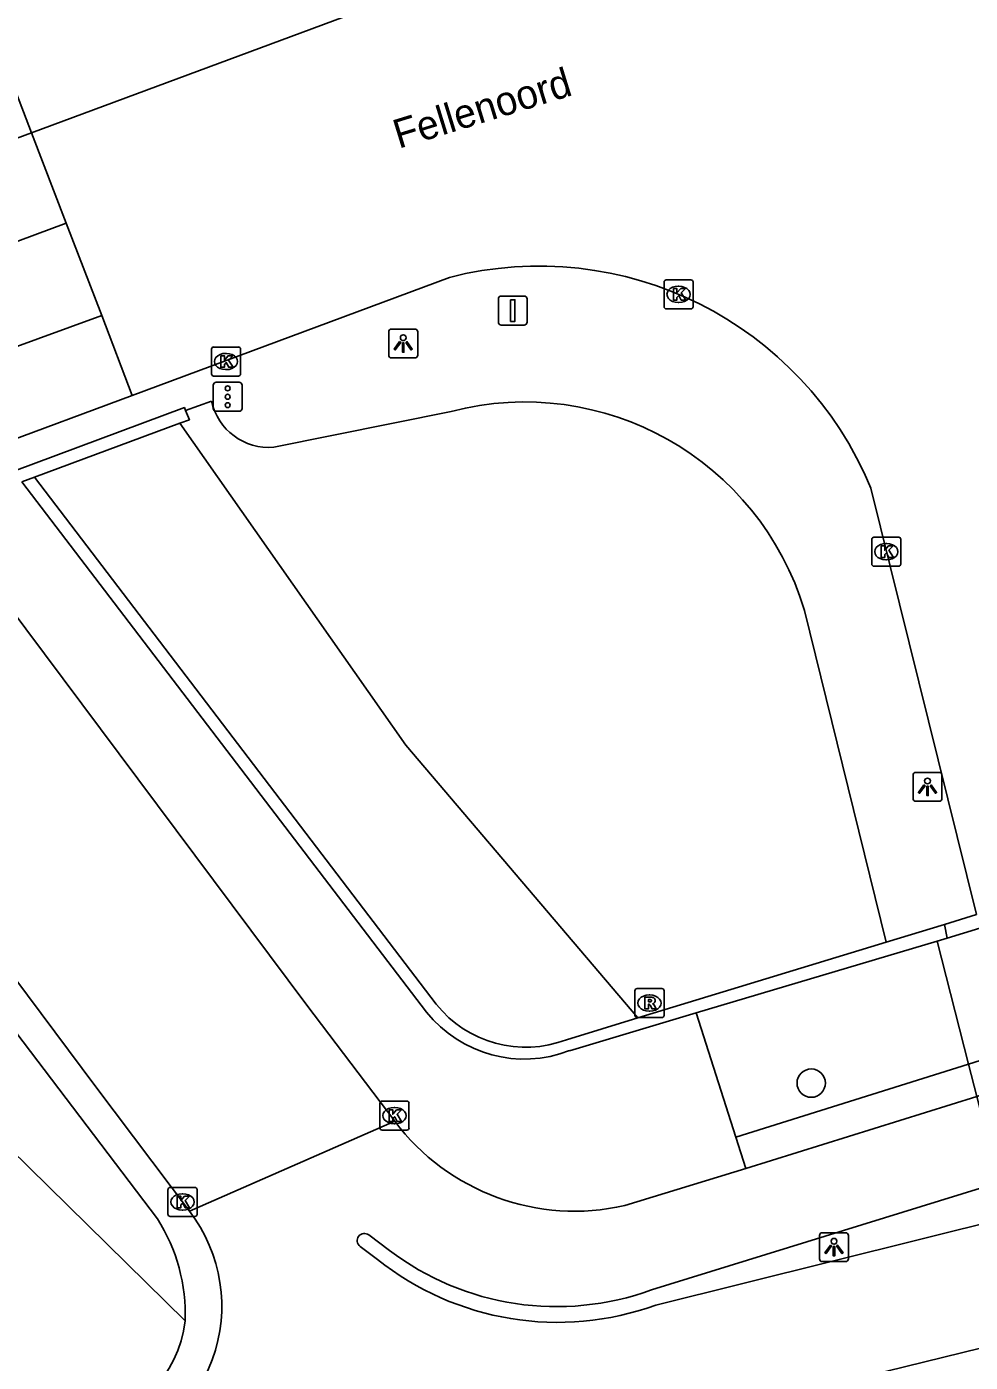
# Model space of a CAD drawing. Extents: x 160806 to 161707, y 383697 to 384148.
# Drawn here: x 160923.82 to 160956.33, y 383760.06 to 383806.1 of the extents above; entities that cross this region are included whole.
import ezdxf

# ---------------------------------------------------------------- set-up
doc = ezdxf.new("R2010")
doc.units = 0
for name, color, linetype in [('IMGEO_Berm_groen', 7, 'Continuous'), ('IMGEO_Boom', 7, 'Continuous'), ('IMGEO_Dek', 7, 'Continuous'), ('IMGEO_Fietspad_open', 7, 'Continuous'), ('IMGEO_Groenvoorziening', 7, 'Continuous'), ('IMGEO_Kolk', 7, 'Continuous'), ('IMGEO_Lichtpunt', 7, 'Continuous'), ('IMGEO_Muur', 7, 'Continuous'), ('IMGEO_Openbare_ruimte_label', 7, 'Continuous'), ('IMGEO_Portaal', 7, 'Continuous'), ('IMGEO_Rijbaan_lokaal_gesloten', 7, 'Continuous'), ('IMGEO_Rioolput', 7, 'Continuous'), ('IMGEO_Verkeersregelinstallatiepaal', 7, 'Continuous'), ('IMGEO_Voetpad_gesloten', 7, 'Continuous'), ('IMGEO_Voetpad_open', 7, 'Continuous')]:
    doc.layers.add(name, color=color, linetype=linetype)

msp = doc.modelspace()

# ---------------------------------------------------------------- linework, layer by layer
at = {"layer": 'IMGEO_Berm_groen'}
msp.add_lwpolyline([(161049.357, 383799.265), (161036.436, 383795.305), (161012.779, 383787.972), (161000, 383783.977), (160984.412, 383779.104), (160968.351, 383774.113), (160967.332, 383773.795), (160957.725, 383770.797), (160956.274, 383770.344), (160948.254, 383767.825)], dxfattribs=at)
at = {"layer": 'IMGEO_Boom'}
msp.add_circle((160950.851, 383769.687), 0.489, dxfattribs=at)
at = {"layer": 'IMGEO_Dek'}
msp.add_lwpolyline([(160956.543, 383775.501), (160955.438, 383775.157), (160955.538, 383774.68), (160955.193, 383774.577), (160956.274, 383770.344), (160956.559, 383769.228)], dxfattribs=at)
at = {"layer": 'IMGEO_Fietspad_open'}
for points in [[(161049.506, 383798.192), (161019.729, 383788.913), (160968.627, 383772.989), (160967.617, 383772.674), (160958.007, 383769.679), (160956.559, 383769.228), (160948.598, 383766.747)], [(160947.606, 383758.324), (160957.999, 383760.873), (160958.651, 383761.038), (160960.089, 383761.401), (160969.85, 383763.865), (160970.809, 383764.107), (160986.327, 383768.025), (161022.896, 383777.258), (161039.914, 383781.555), (161040.772, 383781.738)], [(160945.348, 383762.558), (160957.316, 383766.263), (160958.754, 383766.709), (160966.401, 383769.076)], [(160966.901, 383767.371), (160959.078, 383765.421), (160957.624, 383765.058), (160945.5, 383762.036)], [(160948.598, 383766.747), (160944.425, 383765.465)], [(160935.603, 383764.453), (160936.315, 383763.919)], [(160935.901, 383763.609), (160935.306, 383764.058)]]:
    msp.add_lwpolyline(points, dxfattribs=at)
for centre, radius, start, end in [((160942.706, 383773.033), 7.761, 216.8838, 282.7952), ((160925.172, 383761.997), 5.368, 282.2012, 37.6103), ((160935.454, 383764.256), 0.247, 53.0605, 233.0605), ((160942.106, 383771.399), 9.959, 231.4625, 289.9247), ((160942.082, 383771.536), 9.554, 232.8721, 289.9913)]:
    msp.add_arc(centre, radius, start, end, dxfattribs=at)
at = {"layer": 'IMGEO_Groenvoorziening'}
for points in [[(160944.875, 383771.933), (160936.888, 383781.34), (160929.1, 383792.432)], [(160929.276, 383761.487), (160906.384, 383783.994)]]:
    msp.add_lwpolyline(points, dxfattribs=at)
at = {"layer": 'IMGEO_Kolk'}
for p, q in [((160945.781, 383796.45), (160945.781, 383797.302)), ((160945.856, 383797.376), (160946.708, 383797.376)), ((160946.269, 383797.156), (160946.294, 383797.156)), ((160946.782, 383797.302), (160946.782, 383796.45)), ((160946.708, 383796.376), (160945.856, 383796.376)), ((160946.292, 383796.596), (160946.267, 383796.596)), ((160930.185, 383794.135), (160930.185, 383794.987)), ((160930.26, 383795.061), (160931.112, 383795.061)), ((160930.673, 383794.841), (160930.698, 383794.841)), ((160931.186, 383794.987), (160931.186, 383794.135)), ((160931.112, 383794.061), (160930.26, 383794.061)), ((160930.696, 383794.281), (160930.671, 383794.281)), ((160952.938, 383787.58), (160952.938, 383788.432)), ((160953.013, 383788.506), (160953.865, 383788.506)), ((160953.939, 383788.432), (160953.939, 383787.58)), ((160953.426, 383788.286), (160953.451, 383788.286)), ((160953.865, 383787.506), (160953.013, 383787.506)), ((160953.449, 383787.726), (160953.424, 383787.726)), ((160936.065, 383769.066), (160936.917, 383769.066)), ((160935.99, 383768.14), (160935.99, 383768.992)), ((160936.478, 383768.846), (160936.503, 383768.846)), ((160936.991, 383768.992), (160936.991, 383768.14)), ((160936.501, 383768.286), (160936.476, 383768.286)), ((160936.917, 383768.066), (160936.065, 383768.066)), ((160928.687, 383765.163), (160928.687, 383766.015)), ((160928.762, 383766.089), (160929.614, 383766.089)), ((160929.175, 383765.869), (160929.2, 383765.869)), ((160929.688, 383766.015), (160929.688, 383765.163)), ((160929.614, 383765.089), (160928.762, 383765.089)), ((160929.198, 383765.309), (160929.173, 383765.309))]:
    msp.add_line(p, q, dxfattribs=at)
for points in [[(160945.781, 383796.45), (160945.781, 383797.302)], [(160945.856, 383797.376), (160946.708, 383797.376)], [(160946.782, 383797.302), (160946.782, 383796.45)], [(160946.102, 383797.076), (160946.225, 383797.076), (160946.225, 383796.925), (160946.355, 383797.076), (160946.519, 383797.076), (160946.373, 383796.925), (160946.526, 383796.676), (160946.374, 383796.676), (160946.289, 383796.84), (160946.225, 383796.773), (160946.225, 383796.676), (160946.102, 383796.676), (160946.102, 383797.076)], [(160946.708, 383796.376), (160945.856, 383796.376)], [(160930.185, 383794.135), (160930.185, 383794.987)], [(160930.26, 383795.061), (160931.112, 383795.061)], [(160931.186, 383794.987), (160931.186, 383794.135)], [(160930.506, 383794.761), (160930.629, 383794.761), (160930.629, 383794.61), (160930.759, 383794.761), (160930.923, 383794.761), (160930.777, 383794.61), (160930.93, 383794.361), (160930.778, 383794.361), (160930.693, 383794.525), (160930.629, 383794.458), (160930.629, 383794.361), (160930.506, 383794.361), (160930.506, 383794.761)], [(160931.112, 383794.061), (160930.26, 383794.061)], [(160952.938, 383787.58), (160952.938, 383788.432)], [(160953.013, 383788.506), (160953.865, 383788.506)], [(160953.939, 383788.432), (160953.939, 383787.58)], [(160953.259, 383788.206), (160953.382, 383788.206), (160953.382, 383788.055), (160953.512, 383788.206), (160953.676, 383788.206), (160953.53, 383788.055), (160953.683, 383787.806), (160953.531, 383787.806), (160953.446, 383787.97), (160953.382, 383787.903), (160953.382, 383787.806), (160953.259, 383787.806), (160953.259, 383788.206)], [(160953.865, 383787.506), (160953.013, 383787.506)], [(160936.065, 383769.066), (160936.917, 383769.066)], [(160935.99, 383768.14), (160935.99, 383768.992)], [(160936.311, 383768.766), (160936.434, 383768.766), (160936.434, 383768.615), (160936.564, 383768.766), (160936.728, 383768.766), (160936.582, 383768.615), (160936.735, 383768.366), (160936.583, 383768.366), (160936.498, 383768.53), (160936.434, 383768.463), (160936.434, 383768.366), (160936.311, 383768.366), (160936.311, 383768.766)], [(160936.991, 383768.992), (160936.991, 383768.14)], [(160936.917, 383768.066), (160936.065, 383768.066)], [(160928.687, 383765.163), (160928.687, 383766.015)], [(160928.762, 383766.089), (160929.614, 383766.089)], [(160929.688, 383766.015), (160929.688, 383765.163)], [(160929.008, 383765.789), (160929.131, 383765.789), (160929.131, 383765.638), (160929.261, 383765.789), (160929.425, 383765.789), (160929.279, 383765.638), (160929.432, 383765.389), (160929.28, 383765.389), (160929.195, 383765.553), (160929.131, 383765.486), (160929.131, 383765.389), (160929.008, 383765.389), (160929.008, 383765.789)], [(160929.614, 383765.089), (160928.762, 383765.089)]]:
    msp.add_lwpolyline(points, dxfattribs=at)
for centre, start, end in [((160945.858, 383797.3), 91.552, 178.448), ((160945.858, 383797.3), 91.552, 178.448), ((160946.706, 383797.3), 1.552, 88.448), ((160946.706, 383797.3), 1.552, 88.448), ((160945.858, 383796.452), 181.552, 268.448), ((160945.858, 383796.452), 181.552, 268.448), ((160946.706, 383796.452), 271.552, 358.448), ((160946.706, 383796.452), 271.552, 358.448), ((160930.262, 383794.985), 91.552, 178.448), ((160930.262, 383794.985), 91.552, 178.448), ((160931.11, 383794.985), 1.552, 88.448), ((160931.11, 383794.985), 1.552, 88.448), ((160930.262, 383794.137), 181.552, 268.448), ((160930.262, 383794.137), 181.552, 268.448), ((160931.11, 383794.137), 271.552, 358.448), ((160931.11, 383794.137), 271.552, 358.448), ((160953.015, 383788.43), 91.552, 178.448), ((160953.015, 383788.43), 91.552, 178.448), ((160953.863, 383788.43), 1.552, 88.448), ((160953.863, 383788.43), 1.552, 88.448), ((160953.015, 383787.582), 181.552, 268.448), ((160953.015, 383787.582), 181.552, 268.448), ((160953.863, 383787.582), 271.552, 358.448), ((160953.863, 383787.582), 271.552, 358.448), ((160936.067, 383768.99), 91.552, 178.448), ((160936.067, 383768.99), 91.552, 178.448), ((160936.915, 383768.99), 1.552, 88.448), ((160936.915, 383768.99), 1.552, 88.448), ((160936.067, 383768.142), 181.552, 268.448), ((160936.067, 383768.142), 181.552, 268.448), ((160936.915, 383768.142), 271.552, 358.448), ((160936.915, 383768.142), 271.552, 358.448), ((160928.764, 383766.013), 91.552, 178.448), ((160928.764, 383766.013), 91.552, 178.448), ((160929.612, 383766.013), 1.552, 88.448), ((160929.612, 383766.013), 1.552, 88.448), ((160928.764, 383765.165), 181.552, 268.448), ((160928.764, 383765.165), 181.552, 268.448), ((160929.612, 383765.165), 271.552, 358.448), ((160929.612, 383765.165), 271.552, 358.448)]:
    msp.add_arc(centre, 0.0765, start, end, dxfattribs=at)
for centre, major_axis, ratio, start_param, end_param in [((160946.268, 383796.876), (-0.387, 0.002), 0.722429, 4.712389, 7.853982), ((160946.293, 383796.876), (-0.39, 0.002), 0.717154, 1.570796, 4.712389), ((160930.672, 383794.561), (-0.387, 0.002), 0.722429, 4.712389, 7.853982), ((160930.697, 383794.561), (-0.39, 0.002), 0.717154, 1.570796, 4.712389), ((160953.425, 383788.006), (-0.387, 0.002), 0.722429, 4.712389, 7.853982), ((160953.45, 383788.006), (-0.39, 0.002), 0.717154, 1.570796, 4.712389), ((160936.477, 383768.566), (-0.387, 0.002), 0.722429, 4.712389, 7.853982), ((160936.502, 383768.566), (-0.39, 0.002), 0.717154, 1.570796, 4.712389), ((160929.174, 383765.589), (-0.387, 0.002), 0.722429, 4.712389, 7.853982), ((160929.199, 383765.589), (-0.39, 0.002), 0.717154, 1.570796, 4.712389)]:
    msp.add_ellipse(centre, major_axis=major_axis, ratio=ratio, start_param=start_param, end_param=end_param, dxfattribs=at)
at = {"layer": 'IMGEO_Lichtpunt'}
for p, q in [((160936.295, 383795.584), (160936.295, 383794.777)), ((160936.295, 383795.584), (160936.295, 383794.777)), ((160937.197, 383795.679), (160936.389, 383795.679)), ((160937.197, 383795.679), (160936.389, 383795.679)), ((160937.291, 383794.777), (160937.291, 383795.584)), ((160937.291, 383794.777), (160937.291, 383795.584)), ((160936.389, 383794.683), (160937.197, 383794.683)), ((160936.389, 383794.683), (160937.197, 383794.683)), ((160954.36, 383780.303), (160954.36, 383779.496)), ((160954.36, 383780.303), (160954.36, 383779.496)), ((160955.262, 383780.398), (160954.454, 383780.398)), ((160955.262, 383780.398), (160954.454, 383780.398)), ((160955.356, 383779.496), (160955.356, 383780.303)), ((160955.356, 383779.496), (160955.356, 383780.303)), ((160954.454, 383779.402), (160955.262, 383779.402)), ((160954.454, 383779.402), (160955.262, 383779.402)), ((160952.039, 383764.531), (160951.231, 383764.531)), ((160952.039, 383764.531), (160951.231, 383764.531)), ((160951.137, 383764.436), (160951.137, 383763.629)), ((160951.137, 383764.436), (160951.137, 383763.629)), ((160952.133, 383763.629), (160952.133, 383764.436)), ((160952.133, 383763.629), (160952.133, 383764.436)), ((160951.231, 383763.535), (160952.039, 383763.535)), ((160951.231, 383763.535), (160952.039, 383763.535))]:
    msp.add_line(p, q, dxfattribs=at)
for points in [[(160936.669, 383795.248), (160936.708, 383795.22), (160936.52, 383794.958), (160936.482, 383794.985), (160936.669, 383795.248)], [(160936.771, 383795.2), (160936.818, 383795.2), (160936.818, 383794.878), (160936.771, 383794.878), (160936.771, 383795.2)], [(160936.881, 383795.22), (160936.919, 383795.247), (160937.106, 383794.985), (160937.067, 383794.957), (160936.881, 383795.22)], [(160954.734, 383779.967), (160954.773, 383779.939), (160954.585, 383779.677), (160954.547, 383779.704), (160954.734, 383779.967)], [(160954.836, 383779.919), (160954.883, 383779.919), (160954.883, 383779.597), (160954.836, 383779.597), (160954.836, 383779.919)], [(160954.946, 383779.939), (160954.984, 383779.966), (160955.171, 383779.704), (160955.132, 383779.676), (160954.946, 383779.939)], [(160951.511, 383764.1), (160951.55, 383764.072), (160951.362, 383763.81), (160951.324, 383763.837), (160951.511, 383764.1)], [(160951.613, 383764.052), (160951.66, 383764.052), (160951.66, 383763.73), (160951.613, 383763.73), (160951.613, 383764.052)], [(160951.723, 383764.072), (160951.761, 383764.099), (160951.948, 383763.837), (160951.909, 383763.809), (160951.723, 383764.072)]]:
    msp.add_lwpolyline(points, dxfattribs=at)
for centre in [(160936.794, 383795.382), (160954.859, 383780.101), (160951.636, 383764.234)]:
    msp.add_circle(centre, 0.0994, dxfattribs=at)
for centre, start, end in [((160936.389, 383795.584), 90, 180), ((160936.389, 383795.584), 90, 180), ((160937.197, 383795.584), 0, 90), ((160937.197, 383795.584), 0, 90), ((160936.389, 383794.777), 180, 270), ((160936.389, 383794.777), 180, 270), ((160937.197, 383794.777), 270, 0), ((160937.197, 383794.777), 270, 360), ((160954.454, 383780.303), 90, 180), ((160954.454, 383780.303), 90, 180), ((160955.262, 383780.303), 0, 90), ((160955.262, 383780.303), 0, 90), ((160954.454, 383779.496), 180, 270), ((160954.454, 383779.496), 180, 270), ((160955.262, 383779.496), 270, 0), ((160955.262, 383779.496), 270, 360), ((160951.231, 383764.436), 90, 180), ((160951.231, 383764.436), 90, 180), ((160952.039, 383764.436), 0, 90), ((160952.039, 383764.436), 0, 90), ((160951.231, 383763.629), 180, 270), ((160951.231, 383763.629), 180, 270), ((160952.039, 383763.629), 270, 0), ((160952.039, 383763.629), 270, 360)]:
    msp.add_arc(centre, 0.0946, start, end, dxfattribs=at)
at = {"layer": 'IMGEO_Muur'}
for points in [[(161041.832, 383801.291), (161039.53, 383800.843), (160967.312, 383778.34), (160966.993, 383778.241), (160966.263, 383778.014), (160956.661, 383775.029), (160955.538, 383774.68), (160955.193, 383774.577), (160946.889, 383772.105)], [(160923.377, 383790.783), (160929.252, 383792.972), (160929.293, 383792.872)], [(160929.293, 383792.872), (160929.426, 383792.553), (160929.1, 383792.432)], [(160929.1, 383792.432), (160924.086, 383790.569)], [(160924.086, 383790.569), (160923.655, 383790.409)], [(160937.594, 383772.128), (160923.655, 383790.409)], [(160924.086, 383790.569), (160937.932, 383772.405)], [(160953.439, 383774.547), (160955.438, 383775.157), (160956.543, 383775.501)], [(160944.875, 383771.933), (160953.439, 383774.547)], [(160942.421, 383771.184), (160944.875, 383771.933)], [(160946.889, 383772.105), (160942.522, 383770.805)]]:
    msp.add_lwpolyline(points, dxfattribs=at)
for centre, radius, start, end in [((160941.011, 383774.862), 3.939, 218.5892, 290.9783), ((160940.963, 383774.838), 4.323, 218.8083, 291.1365)]:
    msp.add_arc(centre, radius, start, end, dxfattribs=at)
at = {"layer": 'IMGEO_Portaal'}
for p, q in [((160940.071, 383795.917), (160940.071, 383796.717)), ((160940.071, 383796.717), (160940.071, 383795.917)), ((160940.171, 383796.817), (160940.961, 383796.817)), ((160940.961, 383796.817), (160940.171, 383796.817)), ((160941.061, 383796.717), (160941.061, 383795.917)), ((160941.061, 383795.917), (160941.061, 383796.717)), ((160940.961, 383795.817), (160940.171, 383795.817)), ((160940.171, 383795.817), (160940.961, 383795.817))]:
    msp.add_line(p, q, dxfattribs=at)
msp.add_lwpolyline([(160940.491, 383796.692), (160940.641, 383796.692), (160940.641, 383795.942), (160940.491, 383795.942), (160940.491, 383796.692)], dxfattribs=at)
for centre, start, end in [((160940.171, 383796.717), 90, 180), ((160940.171, 383796.717), 90, 180), ((160940.961, 383796.717), 0, 90), ((160940.961, 383796.717), 360, 90), ((160940.171, 383795.917), 180, 270), ((160940.171, 383795.917), 180, 270), ((160940.961, 383795.917), 270, 0), ((160940.961, 383795.917), 270, 0)]:
    msp.add_arc(centre, 0.1, start, end, dxfattribs=at)
at = {"layer": 'IMGEO_Rijbaan_lokaal_gesloten'}
for points in [[(160923.983, 383802.443), (160957.325, 383814.835)], [(160923.983, 383802.443), (160922.851, 383805.392)], [(160923.983, 383802.443), (160916.701, 383799.758)], [(160925.177, 383799.334), (160923.983, 383802.443)], [(160925.177, 383799.334), (160918.784, 383796.957)], [(160926.402, 383796.144), (160925.177, 383799.334)], [(160938.382, 383797.46), (160927.458, 383793.395)], [(160926.402, 383796.144), (160920.882, 383794.138)], [(160927.458, 383793.395), (160926.402, 383796.144)], [(160922.74, 383791.639), (160927.458, 383793.395)], [(160956.543, 383775.501), (160952.902, 383790.2)], [(160936.499, 383768.375), (160933.47, 383772.374), (160922.492, 383787.071), (160920.782, 383789.342)], [(160913.472, 383786.627), (160926.2, 383769.556), (160929.425, 383765.273)], [(160936.499, 383768.375), (160929.425, 383765.273)]]:
    msp.add_lwpolyline(points, dxfattribs=at)
msp.add_arc((160941.467, 383785.48), 12.371, 22.4294, 104.4404, dxfattribs=at)
at = {"layer": 'IMGEO_Rioolput'}
for p, q in [((160944.778, 383772.02), (160944.778, 383772.872)), ((160944.853, 383772.946), (160945.705, 383772.946)), ((160945.779, 383772.872), (160945.779, 383772.02)), ((160945.266, 383772.726), (160945.291, 383772.726)), ((160945.705, 383771.946), (160944.853, 383771.946)), ((160945.289, 383772.166), (160945.264, 383772.166))]:
    msp.add_line(p, q, dxfattribs=at)
for points in [[(160944.778, 383772.02), (160944.778, 383772.872)], [(160944.853, 383772.946), (160945.705, 383772.946)], [(160945.779, 383772.872), (160945.779, 383772.02)], [(160945.367, 383772.644), (160945.115, 383772.646), (160945.115, 383772.246)], [(160945.115, 383772.246), (160945.239, 383772.246), (160945.239, 383772.408), (160945.25, 383772.408)], [(160945.293, 383772.565), (160945.239, 383772.565), (160945.239, 383772.484)], [(160945.239, 383772.484), (160945.291, 383772.484)], [(160945.297, 383772.379), (160945.368, 383772.246), (160945.508, 383772.246), (160945.443, 383772.372)], [(160945.705, 383771.946), (160944.853, 383771.946)]]:
    msp.add_lwpolyline(points, dxfattribs=at)
for centre, radius, start, end in [((160944.855, 383772.87), 0.0765, 91.552, 178.448), ((160944.855, 383772.87), 0.0765, 91.552, 178.448), ((160945.703, 383772.87), 0.0765, 1.552, 88.448), ((160945.703, 383772.87), 0.0765, 1.552, 88.448), ((160945.249, 383772.355), 0.0533, 26.0293, 88.6989), ((160945.275, 383772.673), 0.19, 274.7715, 282.9687), ((160945.299, 383772.469), 0.0964, 77.0061, 93.1865), ((160945.313, 383772.526), 0.0378, 276.6634, 79.6772), ((160945.366, 383772.534), 0.109, 350.3612, 89.416), ((160945.364, 383772.534), 0.112, 277.5842, 350.9817), ((160945.348, 383772.319), 0.108, 29.5134, 73.7905), ((160944.855, 383772.022), 0.0765, 181.552, 268.448), ((160944.855, 383772.022), 0.0765, 181.552, 268.448), ((160945.703, 383772.022), 0.0765, 271.552, 358.448), ((160945.703, 383772.022), 0.0765, 271.552, 358.448)]:
    msp.add_arc(centre, radius, start, end, dxfattribs=at)
for centre, major_axis, ratio, start_param, end_param in [((160945.265, 383772.446), (-0.387, 0.002), 0.722429, 4.712389, 7.853982), ((160945.29, 383772.446), (-0.39, 0.002), 0.717154, 1.570796, 4.712389)]:
    msp.add_ellipse(centre, major_axis=major_axis, ratio=ratio, start_param=start_param, end_param=end_param, dxfattribs=at)
at = {"layer": 'IMGEO_Verkeersregelinstallatiepaal'}
for p, q in [((160930.248, 383792.945), (160930.248, 383793.745)), ((160930.248, 383793.745), (160930.248, 383792.945)), ((160930.348, 383793.845), (160931.138, 383793.845)), ((160931.138, 383793.845), (160930.348, 383793.845)), ((160931.238, 383793.745), (160931.238, 383792.945)), ((160931.238, 383792.945), (160931.238, 383793.745)), ((160931.138, 383792.845), (160930.348, 383792.845)), ((160930.348, 383792.845), (160931.138, 383792.845))]:
    msp.add_line(p, q, dxfattribs=at)
for centre in [(160930.743, 383793.635), (160930.743, 383793.345), (160930.743, 383793.055)]:
    msp.add_circle(centre, 0.085, dxfattribs=at)
for centre, start, end in [((160930.348, 383793.745), 90, 180), ((160930.348, 383793.745), 90, 180), ((160931.138, 383793.745), 0, 90), ((160931.138, 383793.745), 360, 90), ((160930.348, 383792.945), 180, 270), ((160930.348, 383792.945), 180, 270), ((160931.138, 383792.945), 270, 0), ((160931.138, 383792.945), 270, 0)]:
    msp.add_arc(centre, 0.1, start, end, dxfattribs=at)
at = {"layer": 'IMGEO_Voetpad_gesloten'}
msp.add_lwpolyline([(160956.543, 383775.501), (160955.438, 383775.157), (160955.538, 383774.68), (160955.193, 383774.577), (160956.274, 383770.344), (160956.559, 383769.228), (160957.316, 383766.263), (160957.624, 383765.058), (160958.651, 383761.038), (160959.333, 383758.368)], dxfattribs=at)
at = {"layer": 'IMGEO_Voetpad_open'}
for points in [[(160929.293, 383792.872), (160930.187, 383793.193)], [(160932.332, 383791.606), (160938.441, 383792.84)], [(160912.261, 383786.177), (160928.325, 383765.013)], [(160950.615, 383785.978), (160953.439, 383774.547)], [(160948.254, 383767.825), (160946.889, 383772.105)], [(160948.254, 383767.825), (160948.598, 383766.747)]]:
    msp.add_lwpolyline(points, dxfattribs=at)
for centre, radius, start, end in [((160932.17, 383793.63), 2.031, 192.4361, 274.5714), ((160940.977, 383783.109), 10.056, 16.5778, 104.6057), ((160923.095, 383761.711), 6.185, 357.922, 32.2662), ((160925.158, 383761.971), 4.146, 277.3808, 353.3024)]:
    msp.add_arc(centre, radius, start, end, dxfattribs=at)

# ---------------------------------------------------------------- texts
at = {"layer": 'IMGEO_Openbare_ruimte_label'}
msp.add_text('Fellenoord', height=1, rotation=17.149, dxfattribs=at).set_placement((160936.636, 383801.891))

doc.saveas('drawing.dxf')
